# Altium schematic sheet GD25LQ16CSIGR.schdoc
size 127 x 101 mm
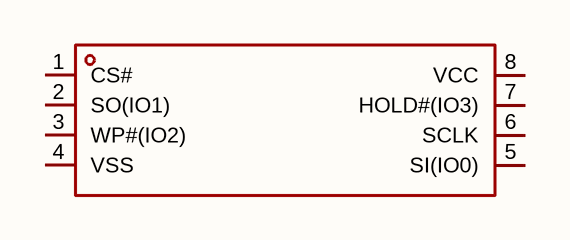
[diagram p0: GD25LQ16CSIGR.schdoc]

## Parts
U?  gd25lq16csigr  [SOIC-8_L5.3-W5.3-P1.27-LS8.0-BL]  (value not drawn)

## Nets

Not connected (* = marked no-connect by the designer): U? 1(CS#) 2(SO(IO1)) 3(WP#(IO2)) 4(VSS) 5(SI(IO0)) 6(SCLK) 7(HOLD#(IO3)) 8(VCC)

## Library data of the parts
U? = gd25lq16csigr: 接口类型:SPI;存储容量:16Mbit;时钟频率(fc):104MHz;; Manufacturer: GigaDevice(兆易创新); AddInBom: yes; ModelId: f83d990ad74f400caf5ac920b7771508; ModelName: SOIC-8_L5.3-W5.3-H1.9-LS7.9-P1.27; ModelTransform: 208.661,311.25654,0,0,0,0,-0.0005,0.0005,0; Interface: SPI; Memory Size: 16Mbit; Clock Frequency: 104MHz; Voltage - Supply: 1.65V~2.1V; Standby Supply Current: 9uA; Program / Erase Cycles: 100000次; Page Programming Time (Tpp): 2.4ms; Block Erase Time(tBE): 800ms@(32KB); Data Retention - TDR (Year): 20年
